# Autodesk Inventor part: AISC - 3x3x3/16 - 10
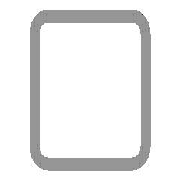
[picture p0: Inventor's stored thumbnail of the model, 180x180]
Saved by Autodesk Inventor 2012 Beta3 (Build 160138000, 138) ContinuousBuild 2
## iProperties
Created: 2010-12
Part Number: AISC - 3x3x3/16 - 10
Material: Steel, Mild
Description: Tube
Document SubType Name: Modeling
Standard: ANSI
Designer: Beta-8540w
Standards Organization: ANSI
Language: en-US
Size Designation: 3x3x3/16
Categories: <MemberInstance><Categories><Category DisplayName="Structural Shapes" InternalName="089c4875-fa83-4c05-b084-43b9cc11f5ed" Mnemonic="GRDR"><CategoryParameter Dis
Stock Number: 3x3x3/16
Density: 7.86 g/cm^3
IsCustomPart: 1
_CCFamilyMember: 9
_CCFamilyDisplayName: ANSI AISC (Square) - Tube
_FrameMemberDoc: Frame Member File
_Version: 15.0.0
_GetPNFromCC: 1
Author: Beta-8540w
G_L: 10.000 in
G_W: 3.000 in
G_H: 3.000 in
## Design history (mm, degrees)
node "Start plane"
node "End plane"
sketch "Sketch"
  geometry: L1 (-38.1, -28.575)-(-38.1, 28.575); L2 (-28.575, 38.1)-(28.575, 38.1); L3 (38.1, 28.575)-(38.1, -28.575); L4 (28.575, -38.1)-(-28.575, -38.1); L5 (-28.575, 33.337)-(28.575, 33.338); L6 (33.338, 28.575)-(33.338, -28.575); L7 (28.575, -33.337)-(-28.575, -33.338); L8 (-33.338, -28.575)-(-33.338, 28.575); L9 (0, 56.102)-(0, -56.102) reference; L10 (-56.102, 0)-(56.102, 0) reference; A1 r 9.525 centre (-28.575, -28.575) between (-38.1, -28.575) and (-28.575, -38.1); A2 r 9.525 centre (-28.575, 28.575) between (-28.575, 38.1) and (-38.1, 28.575); A3 r 9.525 centre (28.575, 28.575) between (38.1, 28.575) and (28.575, 38.1); A4 r 9.525 centre (28.575, -28.575) between (28.575, -38.1) and (38.1, -28.575); A5 r 4.763 centre (-28.575, 28.575) between (-28.575, 33.337) and (-33.338, 28.575); A6 r 4.763 centre (28.575, 28.575) between (33.338, 28.575) and (28.575, 33.338); A7 r 4.763 centre (28.575, -28.575) between (28.575, -33.337) and (33.338, -28.575); A8 r 4.763 centre (-28.575, -28.575) between (-33.338, -28.575) and (-28.575, -33.338)
  constraints: 16 end point, 16 point on circle, 8 centre point, 8 tangent, 4 parallel, 3 equal radius, 2 perpendicular, 7 other
  dimensions: "d10" = 76.2 distance between parallel lines of L2 L4 (= G_H); "d11" = 76.2 distance between parallel lines of L1 L3 (= G_W); "d12" = 4.7625 distance between parallel lines of L3 L6 (= G_T); "d15" = 38.1 distance between parallel lines of L2 L10 (= 0.5 x d10); "d16" = 38.1 distance between parallel lines of L9 L3 (= 0.5 x d11); "d17" = 9.525 radius of A1 (= G_IR)
extrude "Body" new body sketch "Sketch" stored distance "d3" = 254 (= G_L); taper "d4" = 0 deg
node "Driven Length"
  sketch "Sketch3"
    geometry: L1 (0, 0)-(10, 0) reference
    constraints: 2 end point, 1 horizontal
  workplane "Work Plane3"
  sketch "Sketch4"
    geometry: L1 (-2, 0)-(12, 0) reference; L2 (-2, 254)-(12, 254) reference
    dimensions: "d19" = 254 distance between parallel lines of L1 L2 (derived)
body "Solid1"
other parameters: "G_W" = 76.2 [user parameter; used in 1 equation term], "G_H" = 76.2 [user parameter; used in 1 equation term], "G_T" = 4.7625 [user parameter; used in 1 equation term], "G_IR" = 9.525 [user parameter; used in 1 equation term], "G_L" = 254 [user parameter; used in 1 equation term], "G_OFFSET_START" = 0 [user parameter; used in 1 equation term], "G_OFFSET_END" = 0 [user parameter; used in 1 equation term], "d13" = 0 (computed from G_OFFSET_START), "d14" = 254 (= G_OFFSET_END + B_L), "B_L" = 254 [user parameter; used in 1 equation term], "d18" = 90 deg
